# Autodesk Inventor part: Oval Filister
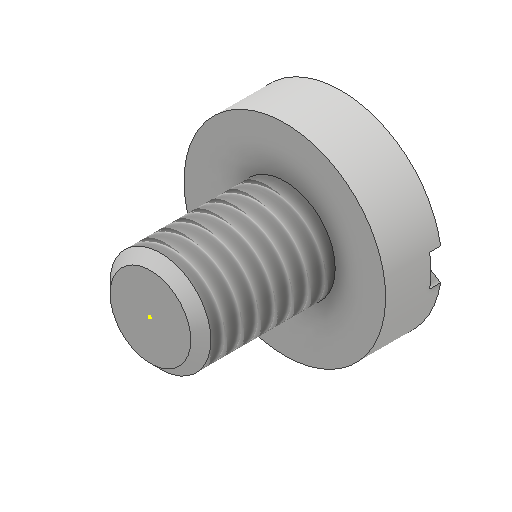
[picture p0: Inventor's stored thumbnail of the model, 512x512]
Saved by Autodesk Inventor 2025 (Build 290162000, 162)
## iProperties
Created: 2016-06
Part Number: Oval Filister
Material: Generic
Document SubType Name: Modeling
Designer: CADCIM
Density: 1 g/cm^3
Appearance: Default
Mass: 0.639925 g
Surface Area: 5.32794 cm^2
Volume: 0.639925 cm^3
Author: CADCIM
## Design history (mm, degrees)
sketch "Sketch2"
  geometry: C1 r 3 at (0, 0); 1 further point
  constraints: 1 centre point, 1 coincident
  dimensions: "d0" = 6 diameter of C1
extrude "Extrusion1" new body sketch "Sketch2" distance "d1" = 8; taper "d2" = 0 deg
revolve "Revolution1" stored, may be unused: angle "d6" = 90 deg
workplane "Work Plane1"
sketch "Sketch5"
  geometry: L1 (6.611, -0.95)-(-6.611, -0.95); L2 (-6.611, -0.95)-(-6.611, 0.95); L3 (-6.611, 0.95)-(6.611, 0.95); L4 (6.611, 0.95)-(6.611, -0.95); L5 (6.611, 0)-(-6.611, 0); 2 further points
  constraints: 10 end point, 3 midpoint, 2 parallel, 1 coincident, 1 horizontal, 1 perpendicular
  dimensions: "d8" = 1.9 distance of L3.end L1.start
extrude "Extrusion2" cut sketch "Sketch5" distance "d9" = 1.9; taper "d10" = 0 deg
thread "Thread1" dims "d11" = 10, "d12" = 0
chamfer "Chamfer1" distance "d13" = 0.6; stored, may be unused: second distance "d14" = 2, angle "d15" = 45 deg
body "Solid1"
sketch "Sketch1"
  geometry: 1 further point
sketch "Sketch3"
  geometry: 1 further point
sketch "Sketch4"
  geometry: L1 (8, 0)-(8, -6); L2 (8, -3)-(8, 3) reference; L3 (8, -6)-(11.35, -6); L4 (12.6, 0)-(8, 0); A1 r 15.025 centre (-2.425, 0) between (11.35, -6) and (12.6, 0); 2 further points
  constraints: 6 end point, 2 midpoint, 2 point on circle, 1 centre point, 1 horizontal, 1 horizontal alignment, 1 perpendicular, 1 point on line, 1 vertical
  dimensions: "d3" = 6 distance of L1.start L1.end; "d4" = 4.6 distance of L4.start L1.start; "d5" = 1.25 horizontal distance of L3.end L4.start
other parameters: "d7" = -4.6
